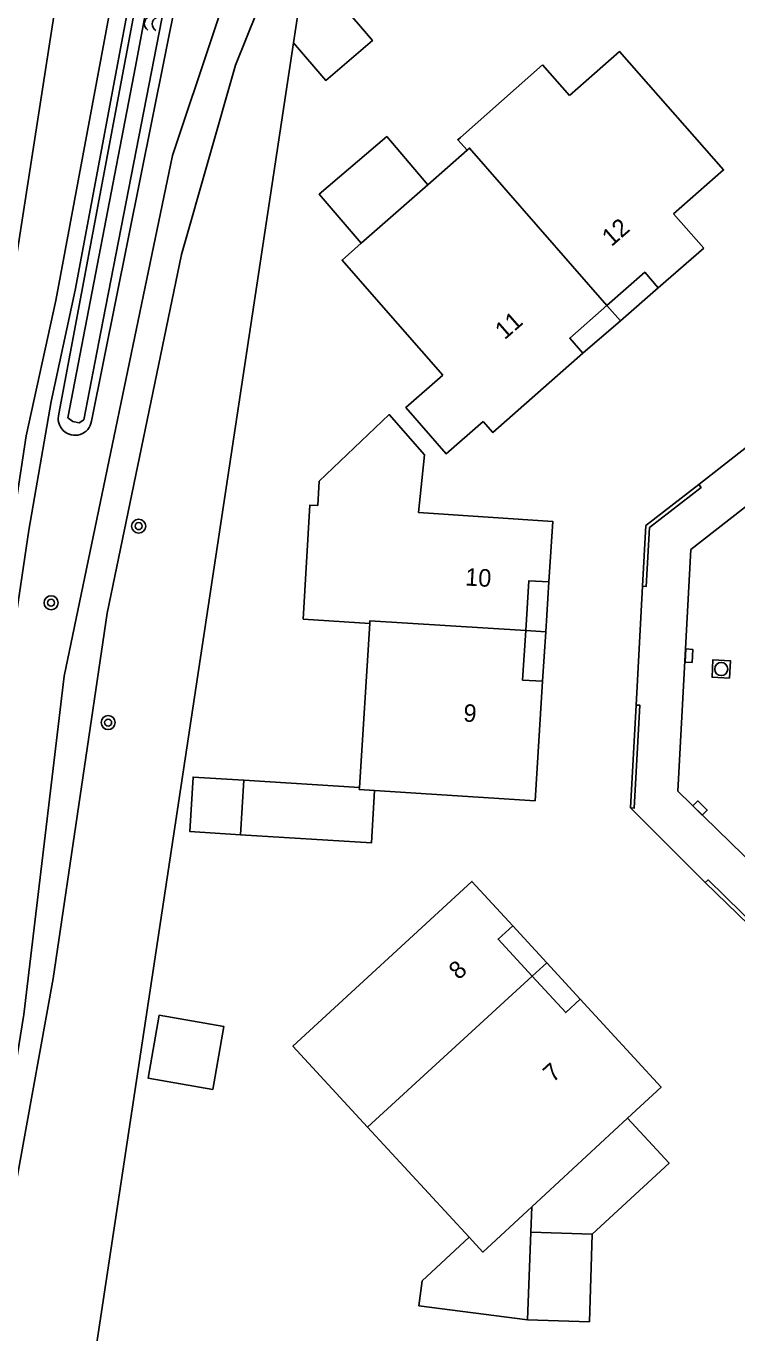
# Model space of a CAD drawing. Extents: x 124000 to 128010, y 398999 to 403000.
# Drawn here: x 126450.7 to 126491.2, y 399045.9 to 399120.5 of the extents above; entities that cross this region are included whole.
import ezdxf

# ---------------------------------------------------------------- set-up
doc = ezdxf.new("R2010")
doc.units = 0
for name, color, linetype in [('gg-afsc-muur', 7, 'Continuous'), ('gg-anno-huisnummerreeks BGT', 7, 'Continuous'), ('gg-bbg-bijgebouw', 7, 'Continuous'), ('gg-bbg-gedigitaliseerde bebouwing', 7, 'Continuous'), ('gg-bbg-gedigitaliseerde bijgebouw', 7, 'Continuous'), ('gg-bbg-hoofdgebouw', 7, 'Continuous'), ('gg-bbg-luifel en loopbrug', 7, 'Continuous'), ('gg-bbg-onder overbouw', 7, 'Continuous'), ('gg-bbg-pand overbouw', 7, 'Continuous'), ('gg-bbg-tussenscheiding', 7, 'Continuous'), ('gg-bbg-tussenscheiding niveau 01', 7, 'Continuous'), ('gg-knt-verharding', 7, 'Continuous'), ('gg-knt-verharding nz', 7, 'Continuous'), ('gg-kntw-bovenkant insteek waterloop', 7, 'Continuous'), ('gg-kntw-waterlijn', 7, 'Continuous'), ('gt-grn-groengrens', 7, 'Continuous'), ('gt-symb-boom', 7, 'Continuous'), ('gt-symb-kolk', 7, 'Continuous'), ('gt-symb-rioolschacht', 7, 'Continuous'), ('gt-symb-watersymbool', 7, 'Continuous')]:
    doc.layers.add(name, color=color, linetype=linetype)

# ---------------------------------------------------------------- blocks, each defined once
blk = doc.blocks.new('gt0-KOLK')
at = {"layer": 'gt-symb-kolk'}
blk.add_lwpolyline([(0, 0), (0.375, 0), (0.375, 0.4), (-0.375, 0.4), (-0.375, 0), (0, 0)], dxfattribs=at)
blk = doc.blocks.new('gt0-RS')
at = {"layer": 'gt-symb-rioolschacht'}
blk.add_lwpolyline([(-0.5, -0.5), (0.5, -0.5), (0.5, 0.5), (-0.5, 0.5)], close=True, dxfattribs=at)
blk.add_circle((0, 0), 0.375, dxfattribs=at)
blk = doc.blocks.new('gt0-BOOM')
at = {"layer": 'gt-symb-boom'}
for radius in [0.4, 0.2]:
    blk.add_circle((0, 0), radius, dxfattribs=at)
blk = doc.blocks.new('gt0-WA')
at = {"layer": 'gt-symb-watersymbool'}
for centre, start, end in [((-0.323, 0.022), 28.07249, 151.92751), ((0.427, 0.422), 208.07248, 331.92751), ((-0.323, -0.428), 28.07249, 151.92751), ((0.427, -0.028), 208.07248, 331.92751)]:
    blk.add_arc(centre, 0.425, start, end, dxfattribs=at)

msp = doc.modelspace()

# ---------------------------------------------------------------- linework, layer by layer
at = {"layer": 'gg-afsc-muur'}
for p, q in [((126454.081, 399041.309), (126465.922, 399119.518)), ((126485.484, 399081.7), (126485.161, 399075.836))]:
    msp.add_line(p, q, dxfattribs=at)
for points in [[(126489.054, 399094.302), (126489.188, 399094.127), (126486.234, 399091.832), (126486.06, 399088.471), (126485.845, 399088.482)], [(126485.845, 399088.482), (126486.033, 399091.952), (126489.054, 399094.302)], [(126485.161, 399075.836), (126485.373, 399075.824), (126485.695, 399081.689), (126485.484, 399081.7)], [(126489.427, 399071.577), (126489.595, 399071.718), (126494.428, 399066.994), (126495.251, 399067.047), (126495.264, 399066.841)], [(126495.264, 399066.841), (126494.361, 399066.767), (126489.427, 399071.577)]]:
    msp.add_lwpolyline(points, dxfattribs=at)
at = {"layer": 'gg-bbg-bijgebouw'}
msp.add_lwpolyline([(126484.988, 399058.118), (126487.365, 399055.548), (126482.975, 399051.488)], dxfattribs=at)
at = {"layer": 'gg-bbg-gedigitaliseerde bebouwing'}
for p, q in [((126481.681, 399116.505), (126480.142, 399118.257)), ((126489.336, 399107.79), (126487.62, 399109.743))]:
    msp.add_line(p, q, dxfattribs=at)
msp.add_lwpolyline([(126481.681, 399116.505), (126484.536, 399119.013), (126490.475, 399112.251), (126487.62, 399109.743)], dxfattribs=at)
at = {"layer": 'gg-bbg-gedigitaliseerde bijgebouw'}
for p, q in [((126463.087, 399077.405), (126462.891, 399074.301)), ((126479.516, 399053.055), (126479.464, 399051.601)), ((126482.975, 399051.488), (126479.464, 399051.601))]:
    msp.add_line(p, q, dxfattribs=at)
msp.add_lwpolyline([(126462.891, 399074.301), (126459.992, 399074.483), (126460.187, 399077.588), (126463.087, 399077.405)], dxfattribs=at)
at = {"layer": 'gg-bbg-hoofdgebouw'}
for p, q in [((126480.142, 399118.257), (126475.443, 399114.104)), ((126475.827, 399113.376), (126473.588, 399111.411)), ((126473.588, 399111.411), (126469.777, 399108.066)), ((126486.744, 399105.526), (126489.336, 399107.79)), ((126470.657, 399104.855), (126474.436, 399100.535)), ((126466.476, 399086.612), (126470.271, 399086.364)), ((126470.271, 399086.364), (126469.676, 399076.99)), ((126475.953, 399051.313), (126470.151, 399057.603))]:
    msp.add_line(p, q, dxfattribs=at)
for points in [[(126475.443, 399114.104), (126475.298, 399113.976), (126475.827, 399113.376)], [(126469.777, 399108.066), (126468.686, 399107.108), (126470.657, 399104.855)], [(126476.752, 399097.888), (126477.291, 399097.271), (126482.443, 399101.786)], [(126476.752, 399097.888), (126474.63, 399096.048), (126472.321, 399098.681), (126474.436, 399100.535)], [(126473.045, 399092.702), (126473.396, 399095.984), (126471.384, 399098.288), (126467.381, 399094.483), (126467.304, 399093.086)], [(126467.304, 399093.086), (126466.85, 399093.116), (126466.476, 399086.612)], [(126480.495, 399088.728), (126480.714, 399092.19), (126473.045, 399092.702)], [(126470.549, 399076.826), (126479.706, 399076.243), (126480.137, 399083.059)], [(126469.676, 399076.99), (126469.669, 399076.882), (126470.549, 399076.826)], [(126470.151, 399057.603), (126465.882, 399062.232), (126476.103, 399071.637), (126478.43, 399069.106)], [(126482.288, 399064.91), (126486.904, 399059.89), (126484.988, 399058.118)], [(126479.516, 399053.055), (126476.726, 399050.475), (126475.953, 399051.313)]]:
    msp.add_lwpolyline(points, dxfattribs=at)
at = {"layer": 'gg-bbg-luifel en loopbrug'}
for p, q in [((126465.922, 399119.518), (126466.528, 399123.521)), ((126463.087, 399077.405), (126469.676, 399076.99)), ((126479.464, 399051.601), (126479.286, 399046.608))]:
    msp.add_line(p, q, dxfattribs=at)
for points in [[(126465.922, 399119.518), (126467.76, 399117.365), (126470.419, 399119.636), (126466.614, 399124.091), (126466.528, 399123.521)], [(126473.588, 399111.411), (126471.24, 399114.161), (126467.384, 399110.868), (126469.777, 399108.066)], [(126462.891, 399074.301), (126470.361, 399073.83), (126470.549, 399076.826)], [(126458.245, 399063.995), (126461.941, 399063.346), (126461.311, 399059.76), (126457.615, 399060.409), (126458.245, 399063.995)], [(126475.953, 399051.313), (126473.257, 399048.823), (126473.073, 399047.405), (126479.286, 399046.608)], [(126479.286, 399046.608), (126482.814, 399046.494), (126482.975, 399051.488)]]:
    msp.add_lwpolyline(points, dxfattribs=at)
at = {"layer": 'gg-bbg-onder overbouw'}
for points in [[(126486.744, 399105.526), (126485.972, 399106.407), (126483.814, 399104.517)], [(126483.814, 399104.517), (126481.685, 399102.651), (126482.443, 399101.786)], [(126480.495, 399088.728), (126479.357, 399088.8), (126479.177, 399085.956)], [(126479.177, 399085.956), (126478.999, 399083.131), (126480.137, 399083.059)], [(126479.547, 399066.221), (126477.598, 399068.341), (126478.43, 399069.106)], [(126482.288, 399064.91), (126481.456, 399064.146), (126479.547, 399066.221)]]:
    msp.add_lwpolyline(points, dxfattribs=at)
at = {"layer": 'gg-bbg-pand overbouw'}
for p, q in [((126486.744, 399105.526), (126484.578, 399103.642)), ((126484.578, 399103.642), (126482.443, 399101.786)), ((126480.495, 399088.728), (126480.315, 399085.885)), ((126480.137, 399083.059), (126480.315, 399085.885)), ((126480.38, 399066.985), (126478.43, 399069.106)), ((126482.288, 399064.91), (126480.38, 399066.985))]:
    msp.add_line(p, q, dxfattribs=at)
at = {"layer": 'gg-bbg-tussenscheiding'}
for p, q in [((126479.547, 399066.221), (126470.151, 399057.603)), ((126479.516, 399053.055), (126484.988, 399058.118))]:
    msp.add_line(p, q, dxfattribs=at)
for points in [[(126483.814, 399104.517), (126475.969, 399113.501), (126475.827, 399113.376)], [(126479.177, 399085.956), (126470.281, 399086.514), (126470.271, 399086.364)]]:
    msp.add_lwpolyline(points, dxfattribs=at)
at = {"layer": 'gg-bbg-tussenscheiding niveau 01'}
for p, q in [((126483.814, 399104.517), (126484.578, 399103.642)), ((126480.315, 399085.885), (126479.177, 399085.956)), ((126480.38, 399066.985), (126479.547, 399066.221))]:
    msp.add_line(p, q, dxfattribs=at)
at = {"layer": 'gg-knt-verharding'}
for p, q in [((126489.054, 399094.302), (126493.554, 399097.829)), ((126485.845, 399088.482), (126485.484, 399081.7)), ((126489.427, 399071.577), (126485.161, 399075.836))]:
    msp.add_line(p, q, dxfattribs=at)
at = {"layer": 'gg-knt-verharding nz'}
msp.add_lwpolyline([(126503.521, 399095.95), (126496.847, 399097.021), (126488.608, 399090.582), (126487.858, 399076.787), (126495.335, 399069.488), (126502.58, 399069.838)], dxfattribs=at)
at = {"layer": 'gg-kntw-bovenkant insteek waterloop'}
for p, q in [((126461.586, 399146.618), (126452.526, 399098.333)), ((126454.38, 399097.907), (126464.14, 399146.36))]:
    msp.add_line(p, q, dxfattribs=at)
msp.add_arc((126453.438, 399098.054), 0.954, 163.00232, 351.11681, dxfattribs=at)
at = {"layer": 'gg-kntw-waterlijn'}
msp.add_lwpolyline([(126453.042, 399098.098), (126456.889, 399118.165), (126462.17, 399146.351), (126462.653, 399146.896), (126463.18, 399146.871), (126463.317, 399146.1), (126454.924, 399103.019), (126453.945, 399097.995), (126453.689, 399097.815), (126453.31, 399097.885), (126453.042, 399098.098)], dxfattribs=at)
at = {"layer": 'gt-grn-groengrens'}
for points in [[(126432.857, 399000), (126438.697, 399039.348), (126443.663, 399066), (126453.391, 399128.528), (126451.871, 399131.365), (126455.114, 399152.647), (126463.931, 399212.54), (126464.539, 399215.58), (126464.542, 399218.587), (126464.697, 399220.401), (126465.251, 399222.596)], [(126441.563, 399000), (126442.662, 399002.637), (126445.751, 399004.568), (126445.365, 399005.727), (126444.848, 399007.567), (126443.434, 399010.747), (126442.662, 399015.381), (126450.514, 399064.037), (126452.831, 399083.345), (126459.01, 399113.08), (126463.644, 399126.982), (126471.624, 399134.062), (126473.812, 399174.094), (126476.493, 399220.429)], [(126443.168, 399000), (126443.692, 399001.221), (126446.781, 399003.152), (126447.553, 399004.697), (126446.395, 399008.172), (126444.464, 399012.034), (126444.144, 399015.345), (126446.009, 399029.411), (126448.326, 399044.858), (126452.187, 399066.097), (126455.277, 399086.95), (126459.524, 399107.416), (126462.614, 399118.229), (126465.703, 399125.952), (126473.04, 399132.002), (126474.585, 399161.35), (126477.674, 399204.987), (126478.427, 399220.056)], [(126435.19, 399002.979), (126436.085, 399002.884), (126438.674, 399018.612), (126446.011, 399062.108), (126447.517, 399069.595), (126450.807, 399091.678), (126452.078, 399099.024), (126453.443, 399105.381), (126458.946, 399134.714), (126461.111, 399146.722), (126465.489, 399153.55), (126465.536, 399153.974), (126468.874, 399163.562), (126467.88, 399163.938), (126464.585, 399153.86), (126460.317, 399147.238), (126458.842, 399139.592), (126452.349, 399104.803), (126450.654, 399097.081), (126449.336, 399088.416), (126446.431, 399069.776), (126442.1, 399045.713), (126435.19, 399002.979)]]:
    msp.add_lwpolyline(points, dxfattribs=at)

# ---------------------------------------------------------------- block references
at = {"layer": 'gt-symb-boom'}
for p in [(126457.077, 399091.917), (126452.077, 399087.542), (126455.335, 399080.7)]:
    msp.add_blockref('gt0-BOOM', p, dxfattribs=at)
at = {"layer": 'gt-symb-kolk'}
for p, rotation in [((126488.293, 399084.529), -92.9796737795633), ((126488.99, 399075.684), -44.27067303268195)]:
    msp.add_blockref('gt0-KOLK', p, dxfattribs=dict(at, rotation=rotation))
at = {"layer": 'gt-symb-rioolschacht', "rotation": 86.84560781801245}
msp.add_blockref('gt0-RS', (126490.338, 399083.758), dxfattribs=at)
at = {"layer": 'gt-symb-watersymbool', "rotation": -92.92247266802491}
msp.add_blockref('gt0-WA', (126457.874, 399121.026), dxfattribs=at)

# ---------------------------------------------------------------- texts
at = {"layer": 'gg-anno-huisnummerreeks BGT'}
for s, rotation, p in [('12', 41.1, (126484.072, 399107.843)), ('11', 41.2, (126477.968, 399102.519)), ('10', 356.4, (126475.696, 399088.532)), ('9', 356.4, (126475.594, 399080.764)), ('8', 42.6, (126475.349, 399065.973)), ('7', 42.6, (126480.735, 399060.115))]:
    msp.add_text(s, height=1, rotation=rotation, dxfattribs=at).set_placement(p)

doc.saveas('drawing.dxf')
